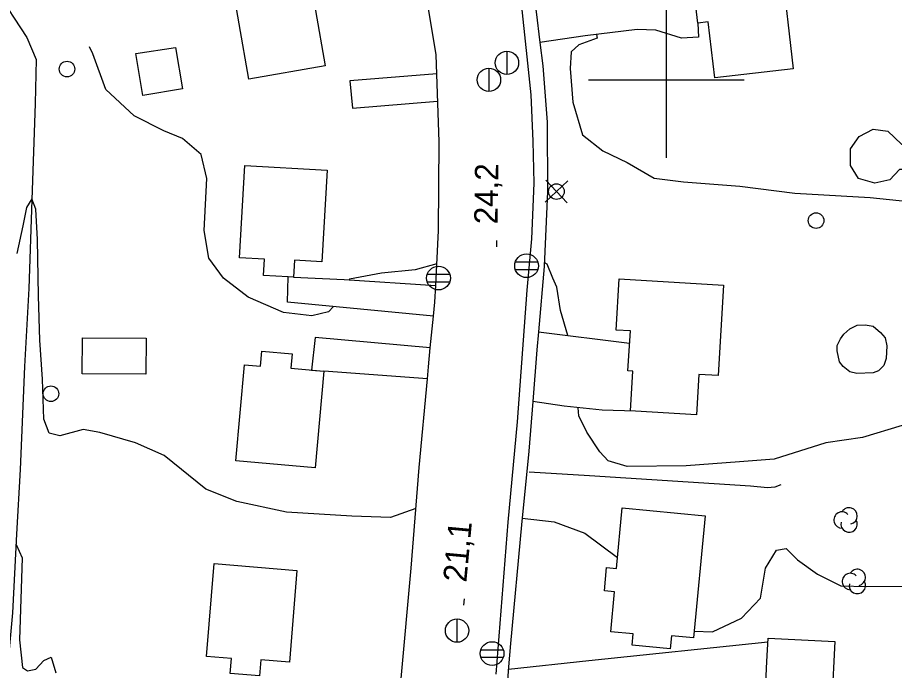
# Model space of a CAD drawing. Extents: x 646142 to 649934, y 5874075 to 5876351.
# Drawn here: x 647516.8 to 647629.3, y 5875124.3 to 5875208 of the extents above; entities that cross this region are included whole.
import ezdxf

# ---------------------------------------------------------------- set-up
doc = ezdxf.new("R2010")
doc.units = 0
for name, color, linetype in [('Niveau 1', 7, 'Continuous'), ('Niveau 19', 7, 'Continuous'), ('Niveau 2', 7, 'Continuous'), ('Niveau 21', 7, 'Continuous'), ('Niveau 22', 7, 'Continuous'), ('Niveau 3', 7, 'Continuous'), ('Niveau 31', 7, 'Continuous'), ('Niveau 36', 7, 'Continuous'), ('Niveau 37', 7, 'Continuous'), ('Niveau 4', 7, 'Continuous'), ('Niveau 44', 7, 'Continuous'), ('Niveau 61', 7, 'Continuous')]:
    doc.layers.add(name, color=color, linetype=linetype)

msp = doc.modelspace()

# ---------------------------------------------------------------- linework, layer by layer
at = {"layer": 'Niveau 1'}
msp.add_lwpolyline([(647516.61, 5875140.4), (647517.4, 5875138.71), (647517.27, 5875134.75), (647517.04, 5875128.21), (647517.44, 5875124.66), (647518.06, 5875124.21), (647519.13, 5875124.43), (647520.17, 5875125.52), (647521.11, 5875125.96), (647521.71, 5875123.96)], dxfattribs=at)
at = {"layer": 'Niveau 19'}
for points in [[(647604.06, 5875207.26), (647604.12, 5875205.45), (647601.95, 5875205.33), (647598.65, 5875206.35), (647596.24, 5875206.44), (647589.57, 5875205.62), (647583.78, 5875204.79)], [(647570.55, 5875200.78), (647559.41, 5875199.87), (647559.77, 5875196.35), (647570.67, 5875197.28)], [(647570.13, 5875169.68), (647551.42, 5875171.49), (647551.51, 5875174.72)], [(647552.17, 5875174.68), (647558.68, 5875174.41), (647570.42, 5875173.61)], [(647583.61, 5875167.7), (647595.29, 5875166.22)], [(647569.73, 5875165.65), (647554.98, 5875166.97), (647554.49, 5875162.79)], [(647569.35, 5875161.64), (647556.09, 5875162.64)], [(647596.03, 5875157.5), (647591.78, 5875157.62), (647586.91, 5875158.14), (647582.87, 5875158.73)], [(647613.03, 5875127.87), (647590.05, 5875125.49), (647579.76, 5875124.37)]]:
    msp.add_lwpolyline(points, dxfattribs=at)
at = {"layer": 'Niveau 2'}
for points in [[(647591.06, 5875205.8), (647591.11, 5875205.34), (647588.79, 5875204.47), (647587.79, 5875203.57), (647587.65, 5875201.45), (647588, 5875197.15), (647589.26, 5875192.96), (647591.86, 5875190.9), (647594.98, 5875189.41), (647598.44, 5875187.38), (647602.2, 5875186.92), (647609.41, 5875186.38), (647616.47, 5875185.47), (647626.14, 5875184.9), (647631.11, 5875184.4)], [(647557.33, 5875170.92), (647556.67, 5875170.23), (647554.52, 5875169.73), (647550.89, 5875170.17), (647546.35, 5875172.13), (647543.2, 5875174.57), (647541.31, 5875177.13), (647540.71, 5875180.68), (647541.05, 5875187.36), (647540.33, 5875190.44), (647537.97, 5875192.49), (647535.56, 5875193.46), (647531.77, 5875195.37), (647528.13, 5875198.74), (647526.43, 5875203.32), (647526.03, 5875204.25)], [(647567.89, 5875145.02), (647564.62, 5875143.89), (647559.67, 5875144.05), (647551.29, 5875144.54), (647544.9, 5875145.92), (647540.96, 5875147.5), (647535.6, 5875151.84), (647531.94, 5875153.45), (647527.33, 5875154.79), (647525.23, 5875155.14), (647522.2, 5875154.36), (647520.85, 5875154.68), (647520.15, 5875156.49), (647520, 5875161.61), (647519.64, 5875166.6), (647519.49, 5875172.3), (647519.36, 5875179.54), (647519.16, 5875183.4), (647518.63, 5875184.72), (647517.93, 5875183.62), (647517.47, 5875181.29), (647516.72, 5875177.73)], [(647570.57, 5875176.4), (647567.79, 5875175.62), (647563.49, 5875175.2), (647559.35, 5875174.45), (647559.32, 5875174.36)], [(647587.37, 5875167.23), (647586.44, 5875170.42), (647585.96, 5875173.41), (647585.43, 5875174.56), (647584.72, 5875176.38), (647584.35, 5875176.56)], [(647630.24, 5875155.67), (647625.14, 5875154.13), (647620.46, 5875153.44), (647613.85, 5875151.35), (647609.37, 5875151.02), (647602.54, 5875150.52), (647594.97, 5875150.4), (647592.52, 5875151.13), (647591.47, 5875152.29), (647589.82, 5875154.82), (647588.79, 5875156.9), (647588.68, 5875157.95)], [(647581.51, 5875143.77), (647585.63, 5875143.32), (647589.55, 5875141.85), (647593.73, 5875138.73)], [(647603.58, 5875129.29), (647605.94, 5875129.2), (647609.62, 5875130.96), (647612.07, 5875133.55), (647612.73, 5875137.39), (647614.12, 5875139.7), (647615.36, 5875139.89), (647616.82, 5875138.45), (647619.4, 5875136.61), (647622.36, 5875135.1), (647625.69, 5875135.05), (647631.88, 5875135.08)]]:
    msp.add_lwpolyline(points, dxfattribs=at)
at = {"layer": 'Niveau 21'}
for points in [[(647570.8, 5875180.66), (647570.85, 5875192.06), (647570.47, 5875203.19), (647568.84, 5875213.05), (647566.83, 5875222.07), (647563.35, 5875233.21), (647559.03, 5875243.69), (647553.65, 5875254.41), (647549.71, 5875260.83), (647544.97, 5875267.29), (647540.01, 5875273.6), (647534.87, 5875279.44), (647528.2, 5875285.69), (647523.55, 5875289.99), (647519.49, 5875292.98), (647513.92, 5875297.3), (647509.02, 5875300.66), (647501.04, 5875305.07), (647487.99, 5875312.13)], [(647581.3, 5875210.63), (647582.11, 5875202.93), (647582.62, 5875198.06), (647582.89, 5875192.13), (647583, 5875186.76), (647582.7, 5875179.62), (647582.12, 5875173.03), (647580.88, 5875156.15), (647579.68, 5875143.28), (647578.78, 5875131.92), (647578.13, 5875123.8)], [(647565.98, 5875123.22), (647567.26, 5875137.4), (647568.32, 5875150.29), (647569.35, 5875161.64), (647569.49, 5875163.19), (647569.73, 5875165.65), (647570.13, 5875169.68), (647570.3, 5875171.48), (647570.42, 5875173.62), (647570.8, 5875180.66)]]:
    msp.add_lwpolyline(points, dxfattribs=at)
at = {"layer": 'Niveau 22'}
msp.add_lwpolyline([(647583.18, 5875209.57), (647583.29, 5875208.71), (647583.78, 5875204.79), (647584.16, 5875201.81), (647584.73, 5875194.58), (647584.78, 5875185.69), (647584.33, 5875176.07), (647583.61, 5875167.7), (647583.4, 5875165.37), (647582.87, 5875158.74), (647582.36, 5875152.38), (647581.43, 5875142.92), (647580.01, 5875127.71), (647579.78, 5875124.72), (647579.25, 5875117.84)], dxfattribs=at)
at = {"layer": 'Niveau 3'}
for p, q in [((647578.27, 5875178.58), (647578.28, 5875179.38)), ((647574.05, 5875132.63), (647574.12, 5875133.43))]:
    msp.add_line(p, q, dxfattribs=at)
at = {"layer": 'Niveau 31'}
for points in [[(647546.45, 5875200.09), (647543.99, 5875214.32), (647553.76, 5875216.02), (647556.23, 5875201.78), (647546.45, 5875200.09)], [(647614.75, 5875214.51), (647616.28, 5875201.42), (647606.21, 5875200.24), (647605.37, 5875207.42), (647604.06, 5875207.26), (647603.36, 5875213.17), (647614.75, 5875214.51)], [(647537.94, 5875198.83), (647532.85, 5875197.99), (647531.98, 5875203.38), (647537.06, 5875204.15), (647537.94, 5875198.83), (647537.94, 5875198.83)], [(647630.16, 5875191.75), (647632.6, 5875191.73), (647632.58, 5875188.48), (647629.92, 5875188.5), (647628.68, 5875187.16), (647626.74, 5875186.76), (647624.63, 5875187.36), (647623.64, 5875189.01), (647623.63, 5875191.13), (647624.74, 5875192.75), (647626.51, 5875193.67), (647628.41, 5875193.42), (647630.16, 5875191.75)], [(647545.27, 5875177.18), (647545.94, 5875189.01), (647556.5, 5875188.42), (647555.84, 5875176.68), (647552.3, 5875176.88), (647552.17, 5875174.68), (647551.51, 5875174.72), (647548.33, 5875174.9), (647548.45, 5875177), (647545.27, 5875177.18)], [(647607.35, 5875173.65), (647606.63, 5875162.07), (647604.18, 5875162.22), (647603.86, 5875157.02), (647596.03, 5875157.5), (647595.4, 5875157.54), (647595.71, 5875162.63), (647595.07, 5875162.67), (647595.39, 5875167.8), (647593.57, 5875167.91), (647593.97, 5875174.47), (647607.35, 5875173.65)], [(647628.06, 5875166.92), (647628.27, 5875165.91), (647628.2, 5875164.26), (647627.88, 5875163.37), (647627.21, 5875162.67), (647626.54, 5875162.43), (647624.43, 5875162.32), (647623.55, 5875162.57), (647622.69, 5875163.22), (647622.23, 5875163.85), (647621.92, 5875165.24), (647621.92, 5875165.93), (647622.35, 5875166.77), (647622.75, 5875167.38), (647623.54, 5875168.09), (647624.47, 5875168.53), (647625.5, 5875168.58), (647626.54, 5875168.41), (647627.48, 5875167.6), (647628.06, 5875166.92)], [(647533.25, 5875162.26), (647525.1, 5875162.3), (647525.12, 5875166.91), (647533.27, 5875166.87), (647533.25, 5875162.26)], [(647554.49, 5875162.79), (647556.09, 5875162.64), (647554.96, 5875150.24), (647544.77, 5875151.16), (647545.89, 5875163.47), (647547.96, 5875163.28), (647548.13, 5875165.2), (647552.01, 5875164.85), (647551.84, 5875163.03), (647556.09, 5875162.64)], [(647604.97, 5875144.1), (647603.5, 5875128.43), (647600.65, 5875128.69), (647600.5, 5875127.03), (647595.6, 5875127.49), (647595.73, 5875128.94), (647592.87, 5875129.21), (647593.36, 5875134.35), (647592.05, 5875134.47), (647592.34, 5875137.47), (647593.6, 5875137.35), (647594.33, 5875145.1), (647604.97, 5875144.1)], [(647541.04, 5875126.05), (647541.99, 5875137.96), (647552.61, 5875137.1), (647551.66, 5875125.31), (647547.98, 5875125.61), (647547.82, 5875123.58), (647544.07, 5875123.88), (647544.23, 5875125.8), (647541.04, 5875126.05)], [(647621.23, 5875120.38), (647612.68, 5875120.8), (647612.91, 5875125.41), (647613.05, 5875128.4), (647621.6, 5875127.99), (647621.23, 5875120.38)]]:
    msp.add_lwpolyline(points, dxfattribs=at)
at = {"layer": 'Niveau 36'}
for p, q in [((647579.57, 5875200.67), (647579.57, 5875203.67)), ((647577.26, 5875198.49), (647577.26, 5875201.49)), ((647587.35, 5875187.04), (647584.45, 5875184.3)), ((647584.53, 5875187.12), (647587.27, 5875184.22)), ((647583.51, 5875176.61), (647580.63, 5875176.61)), ((647580.63, 5875175.69), (647583.51, 5875175.69)), ((647572.22, 5875175.03), (647569.34, 5875175.03)), ((647569.34, 5875174.11), (647572.22, 5875174.11)), ((647573.17, 5875127.86), (647573.17, 5875130.86)), ((647579.09, 5875126.88), (647576.21, 5875126.88)), ((647576.21, 5875125.96), (647579.09, 5875125.96))]:
    msp.add_line(p, q, dxfattribs=at)
for centre, radius in [((647579.56, 5875202.18), 1.5), ((647523.14, 5875201.38), 1), ((647577.25, 5875200), 1.5), ((647585.9, 5875185.67), 1), ((647619.2, 5875181.95), 1), ((647582.07, 5875176.16), 1.52), ((647570.78, 5875174.58), 1.52), ((647521.08, 5875159.75), 1), ((647573.16, 5875129.37), 1.5), ((647577.65, 5875126.43), 1.52)]:
    msp.add_circle(centre, radius, dxfattribs=at)
at = {"layer": 'Niveau 37'}
msp.add_lwpolyline([(647614.67, 5875148.07), (647613.9, 5875147.77), (647612.99, 5875147.67), (647610.79, 5875147.89), (647590.14, 5875149.24), (647582.41, 5875149.68)], dxfattribs=at)
at = {"layer": 'Niveau 4'}
msp.add_lwpolyline([(647441.78, 5875276.12), (647447.7, 5875272.05), (647454.72, 5875266.15), (647462.39, 5875259.4), (647468.94, 5875253.57), (647475.4, 5875247.49), (647481.74, 5875242.67), (647490.65, 5875234.91), (647495.22, 5875230.47), (647500.65, 5875225.44), (647507.14, 5875219.04), (647513.96, 5875211.52), (647517.99, 5875205.44), (647519.19, 5875202.59), (647519.04, 5875196.98), (647518.63, 5875184.59), (647518.23, 5875173.24), (647517.7, 5875163.24), (647517.14, 5875150.03), (647516.67, 5875141.75), (647516.16, 5875131.64), (647515.53, 5875125.05), (647514.76, 5875123.48)], dxfattribs=at)
at = {"layer": 'Niveau 44'}
for centre, start, end in [((647623.44, 5875144.08), 282.2692, 149.7263), ((647622.54, 5875143.55), 44.1154, 269.804), ((647623.44, 5875143.03), 166.9369, 29.6212), ((647624.5, 5875136.2), 282.2692, 149.7263), ((647623.6, 5875135.67), 44.1154, 269.804), ((647624.5, 5875135.15), 166.9369, 29.6212)]:
    msp.add_arc(centre, 1.05, start, end, dxfattribs=at)
at = {"layer": 'Niveau 61'}
for points in [[(647600, 5875210), (647600, 5875200), (647600, 5875190)], [(647590, 5875200), (647600, 5875200), (647610, 5875200)]]:
    msp.add_lwpolyline(points, dxfattribs=at)

# ---------------------------------------------------------------- texts
at = {"layer": 'Niveau 3'}
for s, rotation, p in [('24,2 ', 89.1212, (647578.35, 5875181.46)), ('21,1 ', 84.6949, (647574.35, 5875135.5))]:
    msp.add_text(s, height=3, rotation=rotation, dxfattribs=at).set_placement(p)

doc.saveas('drawing.dxf')
